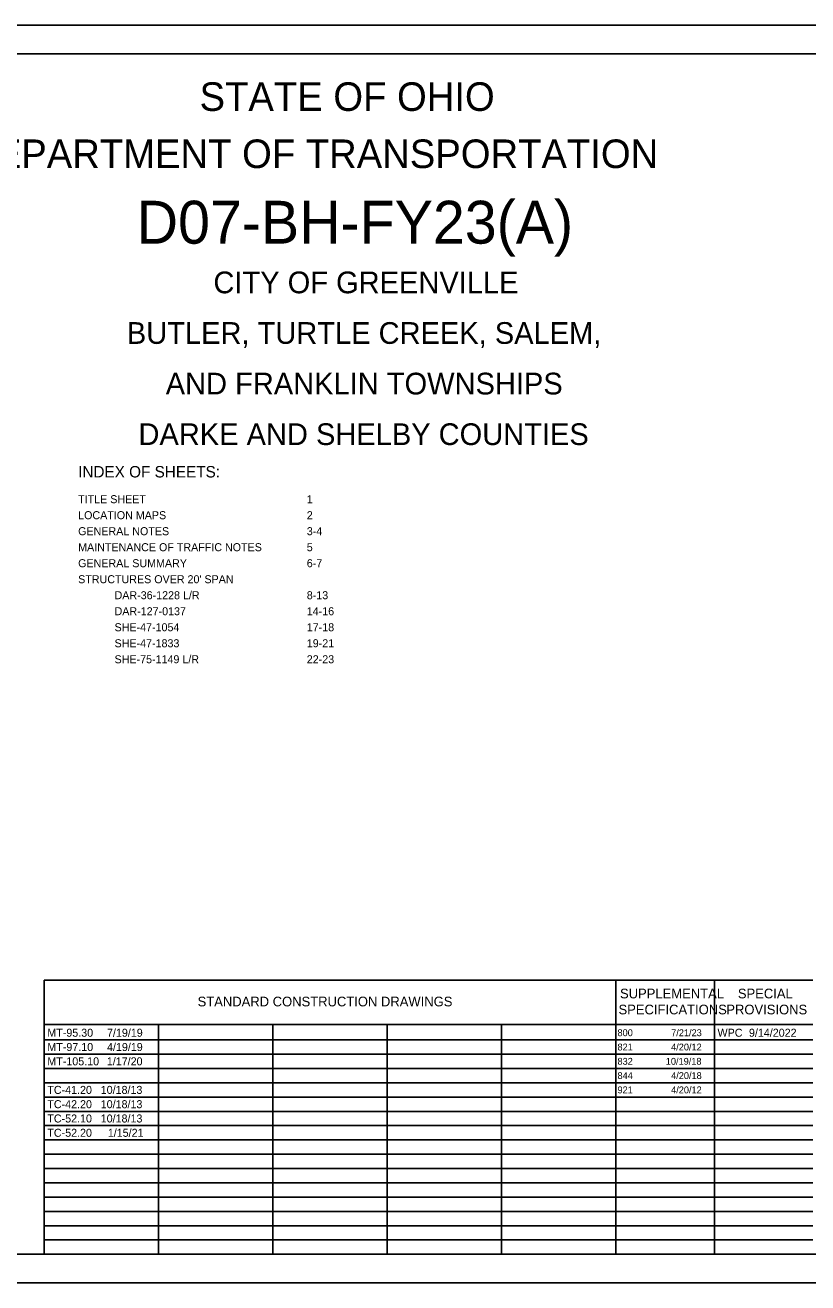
# Model space of a CAD drawing. Extents: x -1.1 to 34, y 0 to 29.8.
# Drawn here: x 10.92 to 24.61, y 0 to 22 of the extents above; entities that cross this region are included whole.
import ezdxf

# ---------------------------------------------------------------- set-up
doc = ezdxf.new("R2010")
doc.units = 0
for name, color, linetype in [('SH_Border', 7, 'Continuous'), ('SH_Cut_Line', 7, 'Continuous'), ('SH_Data', 7, 'Continuous'), ('SH_Text', 7, 'Continuous')]:
    doc.layers.add(name, color=color, linetype=linetype)

msp = doc.modelspace()

# ---------------------------------------------------------------- linework, layer by layer
at = {"layer": 'SH_Border'}
msp.add_lwpolyline([(1.5, 21.5), (33.5, 21.5), (33.5, 0.5), (1.5, 0.5)], close=True, dxfattribs=at)
at = {"layer": 'SH_Cut_Line'}
msp.add_lwpolyline([(0, 0), (34, 0), (34, 22), (0, 22)], close=True, dxfattribs=at)
at = {"layer": 'SH_Data'}
for p, q in [((11.25, 5.292), (24.7, 5.292)), ((11.25, 0.5), (11.25, 5.292)), ((21.25, 0.5), (21.25, 5.292)), ((22.975, 0.5), (22.975, 5.292)), ((11.25, 4.521), (24.7, 4.521)), ((13.25, 0.5), (13.25, 4.521)), ((15.25, 0.5), (15.25, 4.521)), ((17.25, 0.5), (17.25, 4.521)), ((19.25, 0.5), (19.25, 4.521)), ((11.25, 4.25), (24.7, 4.25)), ((11.25, 4), (24.7, 4)), ((11.25, 3.75), (24.7, 3.75)), ((11.25, 3.5), (24.7, 3.5)), ((11.25, 3.25), (24.7, 3.25)), ((11.25, 3), (24.7, 3)), ((11.25, 2.75), (24.7, 2.75)), ((11.25, 2.5), (24.7, 2.5)), ((11.25, 2.25), (24.7, 2.25)), ((11.25, 2), (24.7, 2)), ((11.25, 1.75), (24.7, 1.75)), ((11.25, 1.5), (24.7, 1.5)), ((11.25, 1.25), (24.7, 1.25)), ((11.25, 1), (24.7, 1)), ((11.25, 0.75), (24.7, 0.75))]:
    msp.add_line(p, q, dxfattribs=at)

# ---------------------------------------------------------------- texts
at = {"layer": 'SH_Text'}
for s, height, p in [('STATE OF OHIO', 0.5, (13.968, 20.5)), ('DEPARTMENT OF TRANSPORTATION', 0.5, (9.92, 19.5)), ('D07-BH-FY23(A)', 0.75, (12.868, 18.178)), ('CITY OF GREENVILLE', 0.38, (14.211, 17.31)), ('BUTLER, TURTLE CREEK, SALEM, ', 0.38, (12.696, 16.425)), ('AND FRANKLIN TOWNSHIPS', 0.38, (13.376, 15.54)), ('DARKE AND SHELBY COUNTIES', 0.38, (12.899, 14.655)), ('INDEX OF SHEETS:', 0.2, (11.844, 14.088)), ('TITLE SHEET', 0.14, (11.844, 13.638)), ('1', 0.14, (15.844, 13.638)), ('LOCATION MAPS', 0.14, (11.844, 13.358)), ('2', 0.14, (15.844, 13.358)), ('GENERAL NOTES', 0.14, (11.844, 13.078)), ('3-4', 0.14, (15.844, 13.078)), ('MAINTENANCE OF TRAFFIC NOTES', 0.14, (11.844, 12.798)), ('5', 0.14, (15.844, 12.798)), ('GENERAL SUMMARY', 0.14, (11.844, 12.518)), ('6-7', 0.14, (15.844, 12.518)), ("STRUCTURES OVER 20' SPAN", 0.14, (11.844, 12.238)), ('DAR-36-1228 L/R', 0.14, (12.481, 11.958)), ('8-13', 0.14, (15.844, 11.958)), ('DAR-127-0137', 0.14, (12.481, 11.678)), ('14-16', 0.14, (15.844, 11.678)), ('SHE-47-1054', 0.14, (12.481, 11.398)), ('17-18', 0.14, (15.844, 11.398)), ('SHE-47-1833', 0.14, (12.481, 11.118)), ('19-21', 0.14, (15.844, 11.118)), ('SHE-75-1149 L/R', 0.14, (12.481, 10.838)), ('22-23', 0.14, (15.844, 10.838)), ('SUPPLEMENTAL', 0.17, (21.324, 4.976)), ('SPECIAL', 0.17, (23.386, 4.976)), ('STANDARD CONSTRUCTION DRAWINGS', 0.17, (13.934, 4.836)), ('SPECIFICATIONS', 0.17, (21.298, 4.696)), ('PROVISIONS', 0.17, (23.184, 4.696)), ('MT-95.30', 0.14, (11.305, 4.305)), ('7/19/19', 0.14, (12.349, 4.305)), ('800', 0.12, (21.28, 4.315)), ('7/21/23', 0.12, (22.219, 4.315)), ('WPC', 0.14, (23.03, 4.305)), ('9/14/2022', 0.14, (23.58, 4.305)), ('MT-97.10', 0.14, (11.305, 4.055)), ('4/19/19', 0.14, (12.349, 4.055)), ('821', 0.12, (21.28, 4.065)), ('4/20/12', 0.12, (22.218, 4.065)), ('MT-105.10', 0.14, (11.305, 3.805)), ('1/17/20', 0.14, (12.346, 3.805)), ('832', 0.12, (21.28, 3.815)), ('10/19/18', 0.12, (22.125, 3.815)), ('844', 0.12, (21.28, 3.565)), ('4/20/18', 0.12, (22.218, 3.565)), ('TC-41.20', 0.14, (11.305, 3.305)), ('10/18/13', 0.14, (12.239, 3.305)), ('921', 0.12, (21.28, 3.315)), ('4/20/12', 0.12, (22.218, 3.315)), ('TC-42.20', 0.14, (11.305, 3.055)), ('10/18/13', 0.14, (12.239, 3.055)), ('TC-52.10', 0.14, (11.305, 2.805)), ('10/18/13', 0.14, (12.239, 2.805)), ('TC-52.20', 0.14, (11.305, 2.555)), ('1/15/21', 0.14, (12.363, 2.555))]:
    msp.add_text(s, height=height, dxfattribs=at).set_placement(p)

doc.saveas('drawing.dxf')
